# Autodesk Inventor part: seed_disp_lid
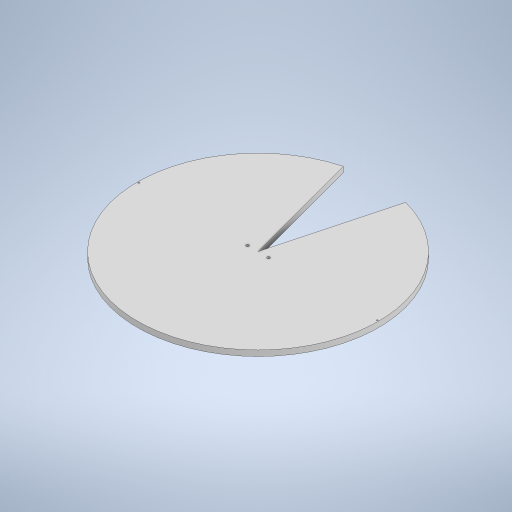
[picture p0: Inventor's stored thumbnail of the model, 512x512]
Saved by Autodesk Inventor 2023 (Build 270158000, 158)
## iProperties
Created: 2022-06
Part Number: seed_disp_lid
Material: Generic
Document SubType Name: Modeling
Designer: prana_p9lsmih
Density: 1 g/cm^3
Appearance: Default
Author: prana_p9lsmih
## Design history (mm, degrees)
sketch "Sketch1"
  geometry: L1 (0, 0)-(11.129, -41.535); L2 (0, 0)-(43, 0); L3 (0, 0)-(-11.129, -41.535); A1 r 43 centre (0, 0) between (11.129, -41.535) and (-11.129, -41.535); 1 further point
  constraints: 6 end point, 2 point on circle, 1 centre point, 1 coincident, 1 equal length, 1 horizontal
  dimensions: "d0" = 86 diameter of A1; "d1" = 75 deg angle of L1 L2
extrude "Extrusion1" new body sketch "Sketch1" distance "d2" = 2; taper "d3" = 0 deg
workplane "Work Plane1"
sketch "Sketch2"
  geometry: C1 r 0.25 at (-42.5, 0); A1 r 43 centre (0, 0) between (-11.129, 41.535) and (11.129, 41.535) reference; 1 further point
  constraints: 1 centre point
  dimensions: "d4" = 0.5 diameter of C1; "d5" = 42.5 distance of C1.centre A1.centre
extrude "Extrusion2" cut sketch "Sketch2" extent not by distance; stored distance "d6" = 0; taper "d7" = 0 deg
mirror "Mirror1"
sketch "Sketch4"
  geometry: C1 r 0.5 at (-3.75, 0); 1 further point
  constraints: 1 centre point
  dimensions: "d12" = 1 diameter of C1; "d13" = 3.75 distance of point (0, 0) C1.centre
extrude "Extrusion4" cut sketch "Sketch4" extent not by distance; stored distance "d14" = 0; taper "d15" = 0 deg
mirror "Mirror3"
body "Solid1"
